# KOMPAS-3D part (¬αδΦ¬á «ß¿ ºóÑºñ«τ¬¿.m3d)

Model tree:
1. Эскиз:1
2. Операция выдавливания:1
     Расстояние 1 = 10; Расстояние 2 = 1.5
3. Эскиз:2
4. Операция выдавливания:2
     Расстояние 1 = 9; Угол 1 = 26; Расстояние 2 = 8.2
5. Эскиз:3
6. Операция выдавливания:3
     Расстояние 1 = 0.3; Расстояние 2 = 8.2
7. Эскиз:4
8. Операция выдавливания:4
     Расстояние 1 = 0.5; Расстояние 2 = 8.2
9. Массив по концентрической сетке:1  (with: Операция выдавливания:4)  (labels: Экземпляр ( 1, 1 ); Экземпляр ( 1, 2 ); Экземпляр ( 1, 3 ); Экземпляр ( 1, 4 ))
     N 2 = 18; Шаг 2 = 360; Номер 2 = 1
10. Эскиз:5
11. Отверстие:1

Referenced files in C:\Program Files\ASCON\KOMPAS-3D V13 Home\Sys\: holelib.lfr
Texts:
  крышка оси звездочки
  Сплав АЛ8  ГОСТ 1583-93
  Отверстие 01
  (вариант 1)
